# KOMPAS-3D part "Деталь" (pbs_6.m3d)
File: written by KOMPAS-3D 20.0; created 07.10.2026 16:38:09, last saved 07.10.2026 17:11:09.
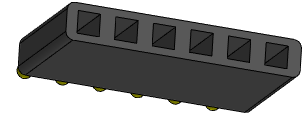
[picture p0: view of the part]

Document properties: Полное имя файла: D:\myProjects\Progect_esp32\box_compas\разъемы\pbs_6.m3d

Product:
- Part/product: Деталь
    Масса: 0.00189261
  - Body: Тело 1
      Масса: 0.00190694

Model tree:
1. Эскиз:1
2. Элемент выдавливания:1
     Расстояние 1 = 8.5
3. Эскиз:2  (with: Элемент выдавливания:1)
4. Элемент выдавливания:2
     Расстояние 1 = 3
5. Массив по сетке:2  (with: Элемент выдавливания:2, Эскиз:2)  (6 pattern instances)
     Шаг 1 = 2.54; Угол раствора = 90
6. Эскиз:3  (with: Элемент выдавливания:1)
7. Элемент выдавливания:3
     Расстояние 2 = 8
8. Массив по сетке:3  (with: Элемент выдавливания:3, Эскиз:3)  (6 pattern instances)
     Шаг 1 = 2.54; Угол раствора = 90; Геометрический массив = 128
9. Скругление:1  (with: Элемент выдавливания:1)
     Радиус = 0.5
